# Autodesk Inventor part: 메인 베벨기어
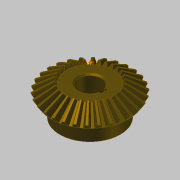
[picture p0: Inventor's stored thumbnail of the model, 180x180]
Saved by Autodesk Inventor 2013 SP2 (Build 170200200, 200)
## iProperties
Created: 2014-10
Part Number: 메인 베벨기어
Material: 강철, 탄소
Document SubType Name: Modeling
Designer: KYOUNG IL JANG
Categories: <?xml version="1.0" encoding="UTF-16"?> <MemberInstance><Categories><FamilyTemplate><FamilyTemplateParameter ValueType="xs:double" Id="1" ObjectReferenceKey="da
Mass: 269.926 g
Surface Area: 108.837 cm^2
Volume: 34.2981 cm^3
Density: 7.87 g/cm^3
CustomPartVersion: 1
Revision Number: 1
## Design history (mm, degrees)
node "맨 위 점"
node "메쉬 평면2"
sketch "톱니 본체 스케치"
  geometry: L1 (0, 0)-(28.669, -21.997); L2 (28.669, -21.997)-(31.109, -18.336); L3 (31.109, -18.336)-(0, 0); L4 (30, -20)-(0, 0); L5 (17.219, -13.212)-(18.685, -11.013); L6 (28.669, -21.997)-(17.219, -13.212); L7 (31.109, -18.336)-(18.685, -11.013); L8 (0, -39.387)-(0, 6.564) reference; L9 (0, -20)-(31.109, -20)
  constraints: 16 end point, 4 point on line, 3 perpendicular, 2 collinear, 1 horizontal alignment, 1 vertical alignment
  dimensions: "d0" = 60 diameter of L4.start L8 (= da_de); "d1" = 57.33744 diameter of L1.end L8 (= da_dfe); "d2" = 62.2188 diameter of L2.end L8 (= da_dae); "d3" = 14.4 distance between parallel lines of L2 L5 (= da_b); "d4" = 18.3359 vertical distance of L2.end L1.start (= da_ve)
revolve "톱니 본체" sketch "톱니 본체 스케치" stored, may be unused: angle "d5" = 90 deg
node "시작점"
node "톱니 평면"
sketch "시작 스케치"
  geometry: L1 (0, -23.505)-(0, 10.645) reference; L2 (-0.709, -2.928)-(0.709, -2.928); A1 r 19.188 centre (-19.457, -7.014) between (-0.709, -2.928) and (-3.232, 3.229); A2 r 19.188 centre (19.457, -7.014) between (3.232, 3.229) and (0.709, -2.928); A3 r 57.403 centre (0, -54.083) between (3.232, 3.229) and (-3.232, 3.229); 1 further point
  constraints: 6 point on circle, 3 centre point, 3 symmetric about line, 2 end point, 1 coincident, 1 perpendicular, 1 other
  dimensions: "d7" = 19.18795 radius of A1 (= fd_rr); "d8" = 19.45712 horizontal distance of point (0, -54.083) A1.centre (= fd_x); "d9" = 47.06905 vertical distance of point (0, -54.083) A1.centre (= fd_y); "d57" = 57.40327 radius of A3 (= 0.5 x fd_dva + 0.3 x da_he); "d58" = 51.15527 distance from line of A3.centre L2 (= 0.5 x fd_dva - 1.12 x da_he)
node "끝점"
  node "끝 평면"
sketch "3D 스케치 오른쪽"
  node "Helical Curve Right" dims "d65" = 229.90621 (computed from da_dm, da_delta, da_beta), "d66" = 31.5, "d67" = 60 (= da_de), "d68" = -9.82794 (= -da_delta), "d69" = 8.10972 (computed from fd_loft, da_delta)
node "끝 평면 오른쪽"
sketch "끝 스케치 오른쪽"
  geometry: L1 (0, -41.54)-(0, 13.178) reference; L2 (-0.422, -1.69)-(0.422, -1.69); A1 r 11.427 centre (-11.587, -4.123) between (-0.422, -1.69) and (-1.925, 1.977); A2 r 11.427 centre (11.587, -4.123) between (1.925, 1.977) and (0.422, -1.69); A3 r 34.184 centre (0, -32.153) between (1.925, 1.977) and (-1.925, 1.977); 1 further point
  constraints: 6 point on circle, 3 centre point, 3 symmetric about line, 2 end point, 1 coincident, 1 perpendicular, 1 other
  dimensions: "d70" = 11.58699 horizontal distance of A3.centre A1.centre (computed from fd_x, fd_ratio); "d71" = 28.03028 vertical distance of point (0, -32.153) A1.centre (computed from fd_y, fd_ratio); "d72" = 11.4267 radius of A1 (computed from fd_rr, fd_ratio); "d73" = 30.46369 distance from line of point (0, -32.153) L2 (computed from d58, fd_ratio); "d74" = 34.18446 radius of A3 (computed from d57, fd_ratio)
feature "로프트 오른쪽" sketch "끝 스케치 오른쪽" dims "d75" = 0, "d77" = 0, "d79" = 0, "d80" = 90 deg, "d85" = 20, "d92" = 90 deg, "d93" = 90 deg, "da_teethtype" = 0 [user parameter]
sketch "3D 스케치 왼쪽"
  node "Helical Curve Left" dims "d26" = 229.90621 (computed from da_dm, da_delta, da_beta), "d27" = 8.10972 (computed from fd_loft, da_delta), "d28" = 60 (= da_de), "d29" = -9.82794 (= -da_delta)
node "끝 평면 왼쪽"
sketch "끝 스케치 왼쪽" dims "d56" = 10.3728 (derived)
  geometry: L1 (0, -43.753)-(0, 15.405) reference; L2 (-0.422, -1.678)-(0.422, -1.678); A1 r 11.427 centre (-11.587, -4.111) between (-0.422, -1.678) and (-1.925, 1.988); A2 r 11.427 centre (11.587, -4.111) between (1.925, 1.988) and (0.422, -1.678); A3 r 34.184 centre (0, -32.142) between (1.925, 1.988) and (-1.925, 1.988); 2 further points; 1 other entity
  constraints: 6 point on circle, 3 centre point, 3 symmetric about line, 2 end point, 1 coincident, 2 other
  dimensions: "d30" = 11.4267 radius of A1 (computed from fd_rr, fd_ratio); "d31" = 11.58699 horizontal distance of point (0, -32.142) A1.centre (computed from fd_x, fd_ratio); "d32" = 28.03028 vertical distance of A1.centre point (0, -32.142) (computed from fd_y, fd_ratio); "d61" = 34.18446 radius of A3 (computed from d57, fd_ratio); "d62" = 30.46369 distance from line of point (0, -32.142) L2 (computed from d58, fd_ratio)
feature "로프트 왼쪽" sketch "끝 스케치 왼쪽" dims "d35" = 0, "d37" = 0, "d39" = 0, "d40" = 90 deg, "d84" = 10, "d90" = 90 deg, "d91" = 90 deg, "da_teethtype" = 0 [user parameter]
sketch "본체 스케치"
  geometry: L1 (0, -35.038)-(0, -19.531) reference; L2 (28.669, -21.997)-(17.219, -13.212) reference; L3 (17.219, -13.212)-(0, -13.212); L4 (28.669, -21.997)-(0, -21.997)
  constraints: 4 end point, 2 perpendicular, 2 point on line
revolve "본체 고정" sketch "본체 스케치" stored, may be unused: angle "d46" = 90 deg
feature "피치 지름" dims angle "d47" = 90 deg
sketch "스케치8"
  geometry: C1 r 22.5 at (0, 0); 1 further point
  constraints: 1 centre point, 1 coincident
  dimensions: "d94" = 45 diameter of C1
extrude "돌출1" join sketch "스케치8" distance "d95" = 13; taper "d96" = 0 deg
sketch "스케치9"
  geometry: 1 further point
hole "구멍1" sketch "스케치9" at (0, 0) diameter "d97" = 17; stored, may be unused: countersink angle "d101" = 90 deg, drill point angle "d103" = 118 deg; dims "d98" = 6, "d99" = 4, "d100" = 2, "d102" = 8
sketch "스케치10"
  geometry: L1 (8.124, 2.5)-(10.8, 2.5); L2 (10.8, 2.5)-(10.8, -2.5); L3 (10.8, -2.5)-(8.124, -2.5); A1 r 8.5 centre (0, 0) between (8.124, 2.5) and (8.124, -2.5) reference; 1 further point
  constraints: 6 end point, 2 parallel, 2 point on circle, 1 horizontal, 1 perpendicular
  dimensions: "d104" = 5 distance of L1.end L2.end; "d112" = 19.3 dimension on A1 L2
extrude "돌출2" cut sketch "스케치10" stored distance "d106" = 10; taper "d107" = 0 deg
chamfer "모따기1" distance "d108" = 1; stored, may be unused: second distance "d109" = 2, angle "d110" = 45 deg
fillet "모깎기1" dims "d111" = 2
body "Solid1"
feature "로프트" dims "d17" = 0, "d18" = 90 deg, "d19" = 0, "d20" = 90 deg, "d89" = 0, "da_teethtype" = 0 [user parameter]
pattern_circular "원형 패턴" dims angle "d22" = 360 deg, "d88" = 0, "da_teethtype" = 0 [user parameter]
pattern_circular "원형 패턴 오른쪽" dims angle "d82" = 360 deg, "da_teethtype" = 0 [user parameter]
pattern_circular "원형 패턴 왼쪽" dims angle "d42" = 360 deg, "da_teethtype" = 0 [user parameter]
sketch "끝 스케치"
  geometry: L1 (0, -15.359)-(0, 6.983) reference; L2 (-0.422, -1.69)-(0.422, -1.69); A1 r 11.427 centre (-11.587, -4.123) between (-0.422, -1.69) and (-1.925, 1.977); A2 r 11.427 centre (11.587, -4.123) between (1.925, 1.977) and (0.422, -1.69); A3 r 34.184 centre (0, -32.153) between (1.925, 1.977) and (-1.925, 1.977); 1 further point
  constraints: 6 point on circle, 3 centre point, 3 symmetric about line, 2 end point, 1 coincident, 1 other
  dimensions: "d12" = 11.4267 radius of A1 (computed from fd_rr, fd_ratio); "d15" = 11.58699 horizontal distance of A1.centre point (0, -32.153) (computed from fd_x, fd_ratio); "d16" = 28.03028 vertical distance of A1.centre point (0, -32.153) (computed from fd_y, fd_ratio); "d59" = 34.18446 radius of A3 (computed from d57, fd_ratio); "d60" = 30.46369 distance from line of A3.centre L2 (computed from d58, fd_ratio)
sketch "Sketch6"
  geometry: L1 (30, -20)-(0, 0) reference; L2 (0, -37.8)-(0, 6.3) reference
body "Srf1"
other parameters: "da_b" = 14.4 [user parameter; used in 2 equation terms], "da_de" = 60 [user parameter; used in 4 equation terms], "da_dae" = 62.2188 [user parameter; used in 2 equation terms], "da_dfe" = 57.33744 [user parameter; used in 1 equation term], "da_le" = 36.05551 [user parameter; used in 1 equation term], "da_omega" = 90 deg [user parameter; used in 1 equation term], "da_beta" = 0 [user parameter; used in 2 equation terms], "da_delta" = 9.82794 [user parameter; used in 8 equation terms], "da_alpha" = 20 deg [user parameter; used in 2 equation terms], "da_he" = 4.4 [user parameter; used in 4 equation terms], "da_ve" = 18.3359 [user parameter; used in 1 equation term], "fd_dv" = 108.16654 (computed from da_de, da_delta) [user parameter; used in 1 equation term], "fd_dva" = 112.16654 (computed from da_dae, da_delta) [user parameter; used in 3 equation terms], "fd_dvb" = 101.6433 (computed from fd_dv, da_alpha) [user parameter; used in 2 equation terms], "da_zv" = 540.83269 [user parameter; used in 1 equation term], "fd_loft" = 14.62 (= da_b + 0.05 x da_he) [user parameter; used in 4 equation terms], "fd_ratio" = 5.95514 (computed from da_le, fd_loft) [user parameter; used in 15 equation terms], "fd_rr" = 19.18795 (computed from fd_dd, fd_dvb) [user parameter; used in 6 equation terms], "fd_angle" = 0.29367 (computed from da_zv) [user parameter; used in 4 equation terms], "fd_x1" = 1.58802 (computed from da_dvw, fd_angle) [user parameter; used in 1 equation term], "fd_y1" = 54.05995 (computed from da_dvw, fd_angle) [user parameter; used in 1 equation term], "fd_x2" = 17.8691 (computed from fd_rr, fd_angle2, fd_angle) [user parameter; used in 1 equation term], "fd_y2" = 6.9909 (computed from fd_rr, fd_angle2, fd_angle) [user parameter; used in 1 equation term], "fd_x" = 19.45712 (= fd_x1 + fd_x2) [user parameter; used in 4 equation terms], "fd_y" = 47.06905 (= fd_y1 - fd_y2) [user parameter; used in 4 equation terms], "fd_angle2" = 3.43555 (computed from fd_dvb, fd_dd, da_alpha) [user parameter; used in 2 equation terms], "fd_dd" = 108.64654 (= fd_dva - 0.8 x da_he) [user parameter; used in 2 equation terms], "da_dvw" = 108.16654 [user parameter; used in 2 equation terms], "d11" = 14.62 (= fd_loft), "da_dm" = 48.01848 [user parameter; used in 2 equation terms], "da_x" = 0 [user parameter], "da_m" = 2 [user parameter], "d48" = 0, "d49" = 0, "d50" = 90 deg (= da_omega), "d51" = 6 deg (computed from da_z), "d52" = 0, "d53" = 0, "d54" = 0
